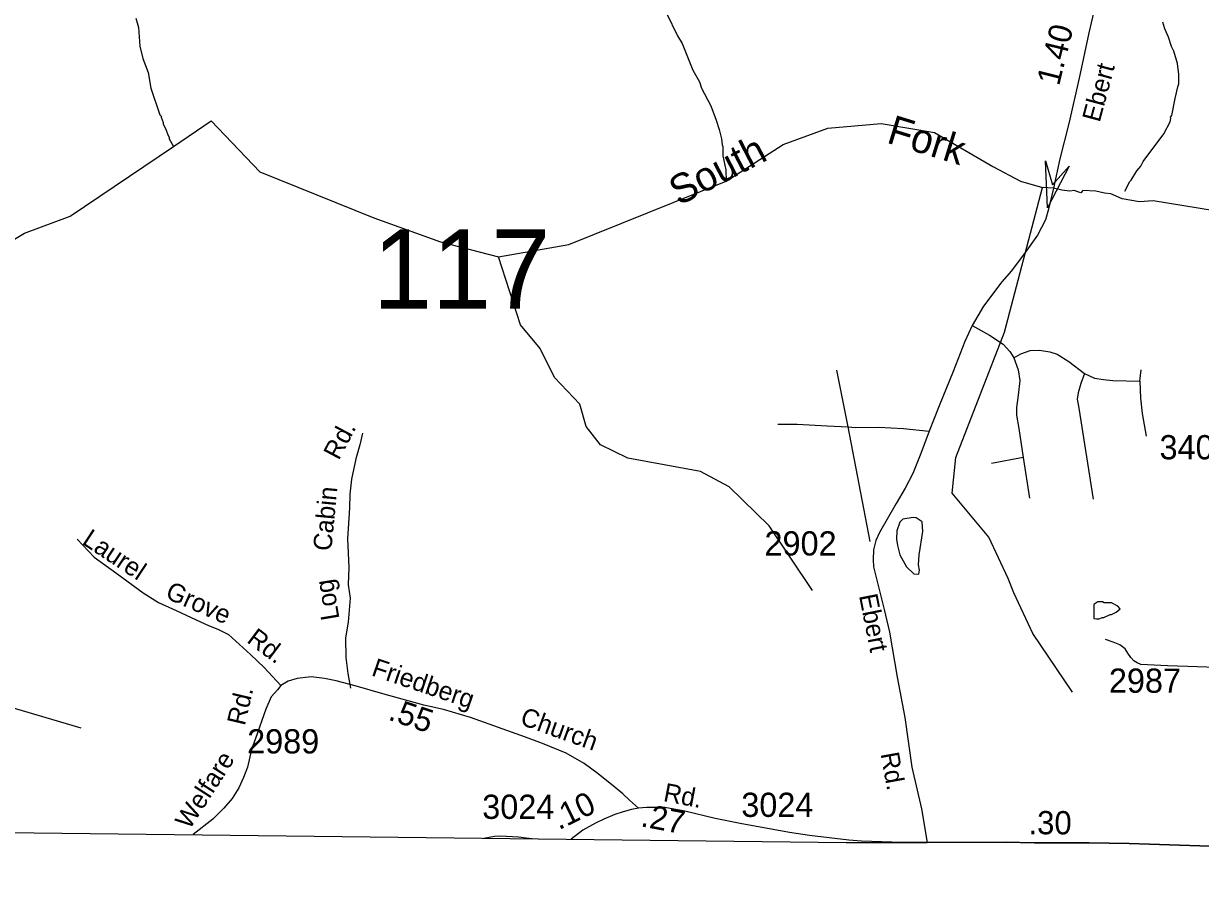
# Model space of a CAD drawing. Extents: x 1547597 to 1699558, y 810033 to 920809.
# Drawn here: x 1609618 to 1615688, y 819952 to 824418 of the extents above; entities that cross this region are included whole.
import ezdxf

# ---------------------------------------------------------------- set-up
doc = ezdxf.new("R2010")
doc.units = 0
for name, color, linetype in [('Exist Boundary Political CountyLine', 7, 'Continuous'), ('Exist Hydrographic Creek Single Shore', 7, 'Continuous'), ('Exist Hydrographic Misc Water Feature', 7, 'Continuous'), ('Exist Road Non-System Type 51', 7, 'Continuous'), ('Exist Road Non-System Type 51 Label', 7, 'Continuous'), ('Exist Road Secondary Mileage Hundredths English Label', 7, 'Continuous'), ('Exist Road Secondary Structure Standard Bridge Attributed CELL', 7, 'Continuous'), ('Exist Road Secondary Structure Standard Bridge Number Label', 7, 'Continuous'), ('Exist Road Secondary Type 51 Attributed', 7, 'Continuous'), ('Exist Road Secondary Type 51 Label', 7, 'Continuous'), ('Exist Road Secondary Type 51 Number Label', 7, 'Continuous'), ('Old_Level_32', 7, 'Continuous')]:
    doc.layers.add(name, color=color, linetype=linetype)

msp = doc.modelspace()

# ---------------------------------------------------------------- linework, layer by layer
at = {"layer": 'Exist Boundary Political CountyLine'}
msp.add_lwpolyline([(1606492.6, 820282.1), (1613860.9, 820194.5), (1614148.1, 820194.4), (1614278.7, 820193.7), (1614685.6, 820195), (1614832.4, 820191.9), (1615113.9, 820191.3), (1615321.1, 820189.2), (1615424.8, 820185.5), (1615839, 820171.5), (1623973.3, 820060), (1623995.2, 820060.7), (1624042.9, 820061.2), (1624114.1, 820060.5), (1624171.2, 820059.7), (1624213.4, 820059.1), (1624257.5, 820058.7), (1624364.8, 820057.3), (1624394.8, 820056.9), (1624433.9, 820056.2), (1624457.5, 820055.9), (1624566.7, 820052.4), (1633697.6, 819951.5)], dxfattribs=at)
at = {"layer": 'Exist Hydrographic Creek Single Shore'}
for points in [[(1608162.5, 822033.9), (1608409.7, 822285.4), (1608763.7, 822628.3), (1609025.7, 822902), (1609345.6, 823171.2), (1609622.7, 823336.3), (1609857.7, 823423.5), (1610391.6, 823783.3), (1610584.7, 823916.5), (1610836.7, 823653.2), (1611424.9, 823414.9), (1611768.8, 823292), (1612067.2, 823213.8)], [(1612067.2, 823213.8), (1612430.7, 823277.7), (1613241.5, 823605.4), (1613535.7, 823794.4), (1613766.6, 823878), (1614041.8, 823902.6), (1614317.2, 823855.3), (1614617.3, 823680), (1614759.9, 823604.4), (1614873.1, 823572.8)], [(1614725.2, 821481.5), (1614696.4, 821555.3), (1614596.7, 821768.2), (1614407.7, 821995.3), (1614426.7, 822178.7), (1614676.7, 822826.8), (1614873.1, 823572.8)], [(1616953.7, 823194.7), (1616893.4, 823203.4), (1616235.8, 823374), (1615443.7, 823504), (1615374.4, 823498.9), (1615284.1, 823514.1), (1615225.9, 823539.4), (1615193, 823543.7), (1615149.1, 823553), (1615081.5, 823555.9), (1615070.6, 823544.9), (1615060.4, 823548.3), (1615036.8, 823555.9), (1615014, 823553.4), (1614972.7, 823558.4), (1614930.5, 823569.4), (1614873.1, 823572.8)], [(1613686.7, 821493.5), (1613463.7, 821827.3), (1613257.7, 822028.4), (1613108.7, 822106.9), (1612734.7, 822176.9), (1612593.7, 822245.4), (1612519.7, 822338.8), (1612487.7, 822454.3), (1612355.7, 822591.6), (1612283.3, 822741.7), (1612180.2, 822864.6), (1612067.2, 823213.8)], [(1615027.7, 820968.4), (1614823.7, 821271.2), (1614725.2, 821481.5)]]:
    msp.add_lwpolyline(points, dxfattribs=at)
at = {"layer": 'Exist Hydrographic Misc Water Feature'}
for points in [[(1612934.2, 824833.5), (1612919, 824776), (1612909.7, 824688.1), (1612911.4, 824664.1), (1612909.2, 824648.1), (1612914.5, 824592), (1612911.9, 824552.1), (1612915.6, 824528.1), (1612934.8, 824471.8), (1612991.2, 824355.1), (1613014.6, 824314.7), (1613070.7, 824178), (1613103.8, 824117.5), (1613115.4, 824085.4), (1613162.1, 823992.7), (1613191.1, 823920.3), (1613206.5, 823872.2), (1613217.7, 823824), (1613221.3, 823792), (1613225.2, 823783.9), (1613224.6, 823735.9), (1613239.6, 823663.8), (1613241.5, 823605.4)], [(1610196.1, 824446), (1610211.4, 824397.8), (1610218, 824301.7), (1610233.2, 824237.6), (1610260.2, 824165.2), (1610275, 824085), (1610321.2, 823946.4), (1610327, 823940.3), (1610327, 823934.3), (1610338.6, 823908.1), (1610338.5, 823900.1), (1610354.1, 823867.9), (1610361.8, 823843.9), (1610369.6, 823831.7), (1610369.5, 823823.7), (1610391.6, 823783.3)], [(1615297.7, 823552.8), (1615323.5, 823602.7), (1615331.6, 823610.6), (1615360.2, 823658.2), (1615380.5, 823681.9), (1615392.8, 823705.7), (1615498.7, 823848.2), (1615531.5, 823911.7), (1615535.9, 823927.7), (1615533.9, 823935.7), (1615540.1, 823943.6), (1615557.2, 824031.3), (1615572, 824091.1), (1615576.2, 824107), (1615576.9, 824155), (1615569.7, 824211.1), (1615550.5, 824275.4), (1615538.9, 824299.5), (1615523.5, 824347.7), (1615504.4, 824390.3), (1615494.3, 824424.5)], [(1614125.7, 821725.9), (1614136.9, 821677.8), (1614172.5, 821615.5), (1614210.5, 821578.8), (1614235.6, 821578), (1614239.2, 821598), (1614234.5, 821626.5), (1614236.6, 821677.7), (1614256.9, 821798.5), (1614253, 821847.1), (1614221.5, 821867.5), (1614206.5, 821869.9), (1614152.9, 821861.6), (1614137.1, 821846.8), (1614122.1, 821801.7), (1614120.5, 821758.3), (1614125.7, 821725.9)], [(1609914.7, 820783.1), (1609458.7, 820917.1), (1609134.6, 821061.5), (1609002.7, 821146.2), (1608953.7, 821239.2), (1608624.6, 821551.8)], [(1615228.9, 821429.6), (1615190.9, 821430.3), (1615183, 821434.4), (1615159, 821434.9), (1615138.8, 821421.3), (1615137.5, 821348.7), (1615151.5, 821347.1), (1615165.5, 821346.8), (1615181.6, 821354.5), (1615189.6, 821354.4), (1615221.9, 821369.8), (1615229.9, 821369.6), (1615254.1, 821381.2), (1615274.4, 821398.9), (1615262.6, 821413.1), (1615228.9, 821429.6)]]:
    msp.add_lwpolyline(points, dxfattribs=at)
at = {"layer": 'Exist Road Non-System Type 51'}
for p, q in [((1613871.6, 822337), (1613813.2, 822629.4)), ((1615376, 822573.7), (1615382.7, 822632)), ((1613984.4, 821745.5), (1613871.6, 822337)), ((1614774.5, 822180.3), (1614610.6, 822148.9)), ((1614774.5, 822180.3), (1614807, 821970.5))]:
    msp.add_line(p, q, dxfattribs=at)
for points in [[(1614510.9, 822861.2), (1614599.4, 822810.5), (1614670.1, 822764.5), (1614704.9, 822726.3), (1614726.2, 822693.8)], [(1614726.2, 822693.8), (1614761, 822714), (1614810.4, 822730.8), (1614858.6, 822733), (1614911.4, 822724.1), (1614948.4, 822711.7), (1615010.1, 822674.7), (1615089.8, 822612.9)], [(1614726.2, 822693.8), (1614748.7, 822630.9), (1614756.5, 822575.9), (1614748.7, 822501.8), (1614739.7, 822436.8), (1614739.7, 822397.5), (1614750.9, 822329), (1614774.5, 822180.3)], [(1615089.8, 822612.9), (1615070.7, 822560.8), (1615057.3, 822513.6), (1615051.7, 822480), (1615060.6, 822433.9), (1615134.7, 821964.8)], [(1615089.8, 822612.9), (1615141.4, 822589.4), (1615188.6, 822582.6), (1615236.8, 822575.9), (1615376, 822573.7)], [(1615376, 822573.7), (1615379.4, 822485), (1615388.3, 822406.5), (1615407.4, 822289.7)], [(1613508.9, 822351.9), (1613608.8, 822350.7), (1613762.5, 822342.8), (1613871.6, 822337)], [(1613871.6, 822337), (1613908.2, 822335), (1614030.1, 822335.3), (1614155.8, 822329.8), (1614289.4, 822316.1)], [(1611366.8, 822305.3), (1611352.3, 822245.4), (1611332, 822172.5), (1611309.9, 822067), (1611300.9, 821991.2), (1611298.7, 821919.3), (1611288.5, 821759.6), (1611295.6, 821613.7), (1611291.4, 821523.2), (1611302.2, 821453.2), (1611291.6, 821330.2), (1611279.1, 821249), (1611279.5, 821147.6), (1611290.4, 821065.6), (1611304.2, 820989.8)], [(1609894.9, 821758.7), (1609981.5, 821664.8), (1610099.5, 821580.5), (1610234.4, 821481.7), (1610313.8, 821431.1), (1610405.3, 821390.1), (1610455.9, 821366), (1610508.9, 821341.9), (1610571.5, 821313), (1610619.6, 821293.8), (1610675, 821267.3), (1610788.2, 821163.7), (1610859.5, 821096.9), (1610944.5, 821003.3)], [(1615769.9, 821096.5), (1615672.2, 821099), (1615518.2, 821105.4), (1615380.3, 821111.6), (1615362.4, 821119.9), (1615344.6, 821130.1), (1615328.8, 821148.4), (1615313.2, 821170.6), (1615299.5, 821192.8), (1615271.9, 821213.2), (1615238.2, 821227.7), (1615199.2, 821240.5)], [(1611991.8, 820216.7), (1612046.4, 820226.6), (1612077.2, 820227.3), (1612170.2, 820223), (1612211, 820218), (1612241.7, 820213.7)]]:
    msp.add_lwpolyline(points, dxfattribs=at)
at = {"layer": 'Exist Road Secondary Structure Standard Bridge Attributed CELL'}
msp.add_lwpolyline([(1615011.9, 823683), (1614899.1, 823466.9), (1614888.7, 823710.5), (1614925.6, 823585.9)], close=True, dxfattribs=at)
at = {"layer": 'Exist Road Secondary Type 51 Attributed'}
for points in [[(1615175.2, 824635.9), (1615112.8, 824369.6), (1615062.1, 824135.8), (1615009.8, 823902), (1614963.5, 823720.5), (1614930.5, 823569.4)], [(1614930.5, 823569.4), (1614905.1, 823460.5), (1614888.2, 823406.1), (1614846.9, 823325.5), (1614784.4, 823237.7), (1614714.4, 823142.3), (1614664.6, 823085.3), (1614569.2, 822960.4), (1614510.9, 822861.2), (1614473, 822777.7), (1614413, 822622.4), (1614341.1, 822445.3), (1614289.4, 822316.1), (1614246.1, 822200.7), (1614204.5, 822096.9), (1614165.7, 822021), (1614119.3, 821941.6), (1614032.4, 821793.5), (1614014.6, 821752.1), (1614002, 821704), (1614000.3, 821652.9), (1614002, 821615.8), (1614056.8, 821395.1), (1614084.7, 821278.6), (1614124.3, 821046.5), (1614163.1, 820837.8), (1614199.3, 820583.1), (1614250.1, 820367.6), (1614278.7, 820193.7)], [(1612789.4, 820370), (1612743.8, 820412.5), (1612708.3, 820445.3), (1612668.5, 820477.8), (1612581.3, 820547.8), (1612509.7, 820600.8), (1612416.2, 820654.6), (1612294.1, 820704.3), (1612207.3, 820737.5), (1611922.7, 820838.3), (1611784, 820879.8), (1611682, 820902.6), (1611470.7, 820960), (1611328.1, 821001.8), (1611231, 821027.3), (1611170.6, 821039.2), (1611101, 821047.9), (1611028.4, 821039.6), (1610982.6, 821025.6), (1610944.5, 821003.3), (1610926.9, 820981.2), (1610895.7, 820945.4), (1610866.9, 820880.7), (1610814.8, 820729.8), (1610794.2, 820674.1), (1610772.7, 820582.9), (1610751.5, 820528.5), (1610727.6, 820475.5), (1610693.4, 820420.1), (1610651, 820371), (1610594.6, 820314), (1610493.1, 820234.5)], [(1612789.4, 820370), (1612754.4, 820363.5), (1612711, 820352), (1612667.9, 820337.5), (1612610, 820314), (1612568.5, 820293.6), (1612503.1, 820256.7), (1612441.5, 820211.3)], [(1614278.7, 820193.7), (1614148.1, 820194.4), (1613939.5, 820200.9), (1613874.3, 820205.2), (1613672.5, 820229.5), (1613568, 820246), (1613447.3, 820267.8), (1613322.6, 820290.6), (1613184.7, 820316.8), (1613028.7, 820355.1), (1612925.9, 820373.7), (1612830.8, 820373.7), (1612789.4, 820370)], [(1615839, 820171.5), (1615424.8, 820185.5), (1615321.1, 820189.2), (1615113.9, 820191.3), (1614824.8, 820191.6), (1614685.6, 820195), (1614278.7, 820193.7)]]:
    msp.add_lwpolyline(points, dxfattribs=at)

# ---------------------------------------------------------------- texts
at = {"layer": 'Exist Road Non-System Type 51 Label'}
for s, rotation, p in [('Rd.', 62.09793, (1611243.7, 822161.2)), ('Cabin', 84.54708, (1611205.2, 821694.7)), ('Laurel', 326.44384, (1609914.3, 821737.2)), ('Grove', 336.25358, (1610343.8, 821456.6)), ('Log', 99.33384, (1611247.6, 821348.1)), ('Rd.', 323.11828, (1610764.4, 821229.8))]:
    msp.add_text(s, height=95, rotation=rotation, dxfattribs=at).set_placement(p)
at = {"layer": 'Exist Road Secondary Mileage Hundredths English Label'}
for s, rotation, p in [('1.40', 76.07963, (1614958.5, 824092.5)), ('.55', 341.37814, (1611493.7, 820828.4)), ('.10', 26.01431, (1612378.5, 820256.2)), ('.27', 349.20845, (1612796.8, 820278)), ('.30', 359.78388, (1614800.8, 820236.4))]:
    msp.add_text(s, height=120, rotation=rotation, dxfattribs=at).set_placement(p)
at = {"layer": 'Exist Road Secondary Structure Standard Bridge Number Label'}
msp.add_text('117', height=410.1, dxfattribs=at).set_placement((1611419.7, 822946.9))
at = {"layer": 'Exist Road Secondary Type 51 Label'}
for s, rotation, p in [('Ebert', 74.88249, (1615168.1, 823904.6)), ('Ebert', 281.27618, (1613926.8, 821467.2)), ('Friedberg', 341.37814, (1611407.5, 821056.4)), ('Rd.', 76.81736, (1610758.6, 820792.8)), ('Church', 340.14423, (1612173.2, 820804.8)), ('Welfare', 57.25163, (1610473.7, 820256)), ('Rd.', 280.35768, (1614038, 820651.4)), ('Rd.', 349.20845, (1612913.7, 820408))]:
    msp.add_text(s, height=95, rotation=rotation, dxfattribs=at).set_placement(p)
at = {"layer": 'Exist Road Secondary Type 51 Number Label'}
for s, p in [('3405', (1615477.2, 822170)), ('2902', (1613439.6, 821674)), ('2987', (1615216, 820966.1)), ('2989', (1610771.1, 820653.1)), ('3024', (1611983.6, 820315.5)), ('3024', (1613319.9, 820325.7))]:
    msp.add_text(s, height=125, dxfattribs=at).set_placement(p)
at = {"layer": 'Old_Level_32'}
for s, rotation, p in [('Fork', 342.87414, (1614063.9, 823804.8)), ('South', 27.40972, (1612997.9, 823476))]:
    msp.add_text(s, height=150, rotation=rotation, dxfattribs=at).set_placement(p)

doc.saveas('drawing.dxf')
